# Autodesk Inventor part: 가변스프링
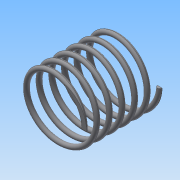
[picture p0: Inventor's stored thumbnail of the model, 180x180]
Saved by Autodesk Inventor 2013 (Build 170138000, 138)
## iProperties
Created: 2018-02
Part Number: 가변스프링
Material: 일반
Document SubType Name: Modeling
Designer: Administrator
Density: 1 g/cm^3
Mass: 5.22833 g
Surface Area: 70.8526 cm^2
Volume: 5.22833 cm^3
Author: Administrator
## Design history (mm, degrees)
sketch "스케치1"
  geometry: L1 (0, 0)-(20, 0); L2 (20, 0)-(20, 47.25); L3 (20, 47.25)-(0, 47.25); L4 (0, 47.25)-(0, 0); C1 r 1.5 at (20, 0)
  constraints: 8 end point, 2 parallel, 1 centre point, 1 horizontal, 1 perpendicular
  dimensions: "d0" = 3 diameter of C1; "d1" = 40 diameter of L2 L4; "d2" = 47.25 distance of L3.end L1.start (derived)
feature "코일1" sketch "스케치1" pitch "d3" = 10; turns "d5" = 6; dims "d4" = 47.25 (= d2), "d6" = 0, angle "d7" = 90 deg, angle "d8" = 90 deg, "d9" = 0, "d10" = 0
sketch "스케치2"
  geometry: L1 (-25, 47.25)-(25, 47.25); L2 (25, 47.25)-(25, 0); L3 (25, 0)-(-25, 0); L4 (-25, 0)-(-25, 47.25); 6 further points
  constraints: 8 end point, 2 horizontal alignment, 2 parallel, 2 point on line, 1 horizontal, 1 midpoint, 1 perpendicular, 1 vertical alignment
  dimensions: "d11" = 50 distance between parallel lines of L4 L2
extrude "돌출1" sketch "스케치2" stored distance "d13" = 0; taper "d14" = 0 deg
node "솔리드1"
